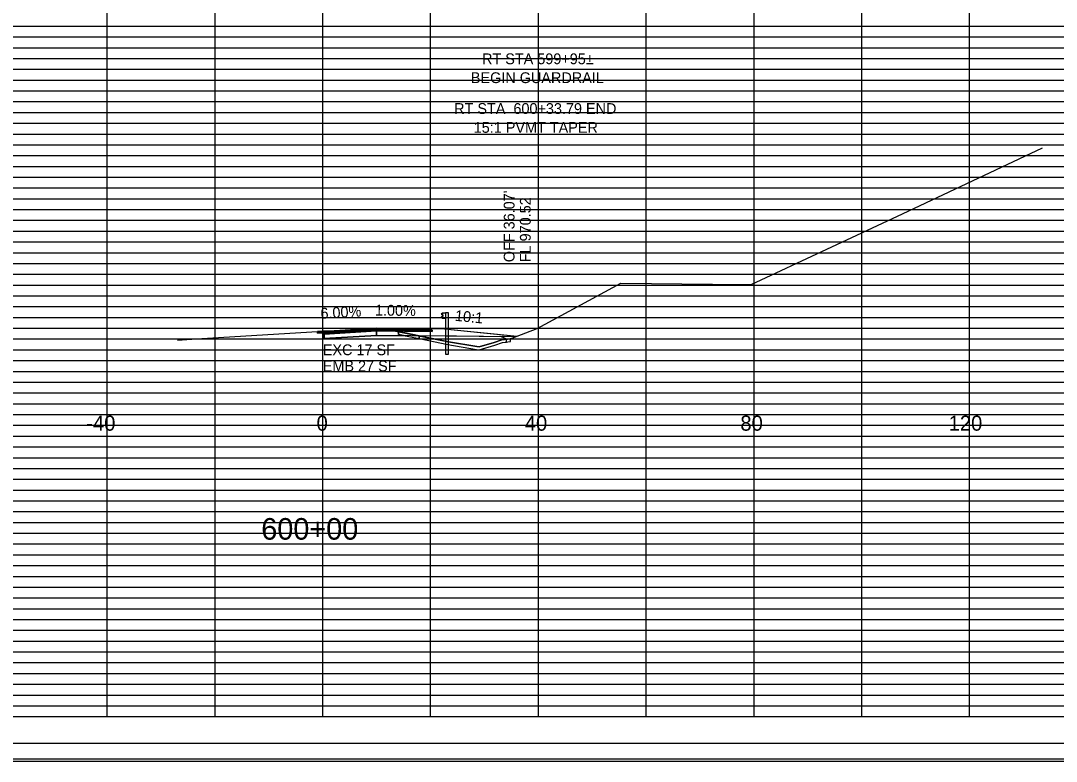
# Model space of a CAD drawing. Extents: x 2313580 to 2322968, y 282099 to 303247.
# Drawn here: x 2317145.2 to 2317337.4, y 287579.4 to 287716.7 of the extents above; entities that cross this region are included whole.
import ezdxf

# ---------------------------------------------------------------- set-up
doc = ezdxf.new("R2010")
doc.units = 0
for name, color, linetype in [('DESIGN - CENTERLINE - Proposed', 7, 'Continuous'), ('DESIGN - DRAINAGE - Text', 7, 'Continuous'), ('DESIGN - EARTHWORK - Excavation Limit Lines', 7, 'Continuous'), ('DESIGN - EARTHWORK - Shapes', 7, 'Continuous'), ('DESIGN - SCRATCH - User 5', 7, 'Continuous'), ('DESIGN - SHEET - Light Grid', 7, 'Continuous'), ('DESIGN - SHEET - Linework', 7, 'Continuous'), ('DESIGN - SHEET - Plot Shape', 7, 'Continuous'), ('DESIGN - TRANSPORTATION - Text', 7, 'Continuous'), ('DESIGN - TYPICAL - Finished Grade and Subgrade', 7, 'Continuous'), ('DESIGN - TYPICAL - Finished Grade Slopes Text', 7, 'Continuous'), ('DESIGN - TYPICAL - Guardrail', 7, 'Continuous'), ('DESIGN - TYPICAL - Text', 7, 'Continuous'), ('Scratch Level', 7, 'Continuous'), ('SURVEY - GROUND - Top of Ground', 7, 'Continuous')]:
    doc.layers.add(name, color=color, linetype=linetype)

# ---------------------------------------------------------------- blocks, each defined once
blk = doc.blocks.new('GRTYP')
at = {"layer": 'DESIGN - CENTERLINE - Proposed'}
for p, q in [((0.162, 0.37), (0.162, 0.37)), ((0.162, 0.37), (0.162, 0.37)), ((0.264, 0.37), (0.264, 0.37)), ((0.264, 0.37), (0.264, 0.37))]:
    blk.add_line(p, q, dxfattribs=at)
for points in [[(0.059, 0.567), (0.04, 0.563), (0.004, 0.539), (0, 0.531), (0.004, 0.523), (0.055, 0.492), (0.059, 0.484), (0.059, 0.464), (0.055, 0.456), (0.004, 0.425), (0, 0.417), (0.004, 0.409), (0.04, 0.385), (0.059, 0.382)], [(0.162, 0.374), (0.059, 0.374), (0.059, 0.574), (0.162, 0.574)], [(0.264, -0.126), (0.264, 0.574), (0.162, 0.574), (0.162, -0.075)], [(0.162, -0.075), (0.162, -0.949), (0.264, -0.949), (0.264, -0.122)]]:
    blk.add_lwpolyline(points, dxfattribs=at)

msp = doc.modelspace()

# ---------------------------------------------------------------- linework, layer by layer
at = {"layer": 'DESIGN - EARTHWORK - Shapes'}
for points in [[(2317216.53, 287658.28), (2317215.34, 287658.52), (2317215.34, 287659.03), (2317213.53, 287659.39), (2317207.54, 287659.33), (2317201.3, 287659.13), (2317200.3, 287659.07), (2317200.3, 287658.97), (2317200.3, 287658.76), (2317201.51, 287658.82), (2317201.51, 287658.57), (2317201.51, 287657.74), (2317211.26, 287658.33)], [(2317219.17, 287658.25), (2317224.59, 287657.15), (2317229.87, 287656.25), (2317230.27, 287656.2), (2317233.05, 287657.02), (2317234.49, 287657.49), (2317236.03, 287657.69), (2317237.03, 287658.07)]]:
    msp.add_lwpolyline(points, close=True, dxfattribs=at)
at = {"layer": 'DESIGN - SCRATCH - User 5'}
for points in [[(2317219.17, 287658.25), (2317215.34, 287659.03), (2317215.34, 287658.52), (2317219.17, 287657.74)], [(2317219.17, 287658.25), (2317215.34, 287659.03), (2317215.34, 287658.52), (2317219.17, 287657.74)], [(2317219.17, 287657.74), (2317224.5, 287656.66), (2317229.79, 287655.75), (2317230.31, 287655.69), (2317233.2, 287656.54), (2317234.6, 287657), (2317235.38, 287657.1), (2317235.38, 287657.61), (2317234.49, 287657.49), (2317233.05, 287657.02), (2317230.27, 287656.2), (2317229.87, 287656.25), (2317224.59, 287657.15), (2317219.17, 287658.25)], [(2317219.17, 287657.74), (2317224.5, 287656.66), (2317229.79, 287655.75), (2317230.31, 287655.69), (2317233.2, 287656.54), (2317234.6, 287657), (2317236.11, 287657.2), (2317236.11, 287657.72), (2317236.03, 287657.69), (2317234.49, 287657.49), (2317233.05, 287657.02), (2317230.27, 287656.2), (2317229.87, 287656.25), (2317224.59, 287657.15), (2317219.17, 287658.25)]]:
    msp.add_lwpolyline(points, close=True, dxfattribs=at)
at = {"layer": 'DESIGN - SHEET - Light Grid'}
for p, q in [((2317041.28, 287715.67), (2317201.28, 287715.67)), ((2317201.28, 287715.67), (2317361.28, 287715.67)), ((2317041.28, 287713.67), (2317201.28, 287713.67)), ((2317201.28, 287713.67), (2317361.28, 287713.67)), ((2317041.28, 287711.67), (2317201.28, 287711.67)), ((2317201.28, 287711.67), (2317361.28, 287711.67)), ((2317041.28, 287709.67), (2317201.28, 287709.67)), ((2317201.28, 287709.67), (2317361.28, 287709.67)), ((2317041.28, 287705.67), (2317201.28, 287705.67)), ((2317201.28, 287705.67), (2317361.28, 287705.67)), ((2317041.28, 287703.67), (2317201.28, 287703.67)), ((2317201.28, 287703.67), (2317361.28, 287703.67)), ((2317041.28, 287701.67), (2317201.28, 287701.67)), ((2317201.28, 287701.67), (2317361.28, 287701.67)), ((2317041.28, 287699.67), (2317201.28, 287699.67)), ((2317201.28, 287699.67), (2317361.28, 287699.67)), ((2317041.28, 287697.67), (2317201.28, 287697.67)), ((2317201.28, 287697.67), (2317361.28, 287697.67)), ((2317041.28, 287695.67), (2317201.28, 287695.67)), ((2317201.28, 287695.67), (2317361.28, 287695.67)), ((2317041.28, 287693.67), (2317201.28, 287693.67)), ((2317201.28, 287693.67), (2317361.28, 287693.67)), ((2317041.28, 287691.67), (2317201.28, 287691.67)), ((2317201.28, 287691.67), (2317361.28, 287691.67)), ((2317041.28, 287689.67), (2317201.28, 287689.67)), ((2317201.28, 287689.67), (2317361.28, 287689.67)), ((2317041.28, 287685.67), (2317201.28, 287685.67)), ((2317201.28, 287685.67), (2317361.28, 287685.67)), ((2317041.28, 287683.67), (2317201.28, 287683.67)), ((2317201.28, 287683.67), (2317361.28, 287683.67)), ((2317041.28, 287681.67), (2317201.28, 287681.67)), ((2317201.28, 287681.67), (2317361.28, 287681.67)), ((2317041.28, 287679.67), (2317201.28, 287679.67)), ((2317201.28, 287679.67), (2317361.28, 287679.67)), ((2317041.28, 287677.67), (2317201.28, 287677.67)), ((2317201.28, 287677.67), (2317361.28, 287677.67)), ((2317041.28, 287675.67), (2317201.28, 287675.67)), ((2317201.28, 287675.67), (2317361.28, 287675.67)), ((2317041.28, 287673.67), (2317201.28, 287673.67)), ((2317201.28, 287673.67), (2317361.28, 287673.67)), ((2317041.28, 287671.67), (2317201.28, 287671.67)), ((2317201.28, 287671.67), (2317361.28, 287671.67)), ((2317041.28, 287669.67), (2317201.28, 287669.67)), ((2317201.28, 287669.67), (2317361.28, 287669.67)), ((2317041.28, 287665.67), (2317201.28, 287665.67)), ((2317201.28, 287665.67), (2317361.28, 287665.67)), ((2317041.28, 287663.67), (2317201.28, 287663.67)), ((2317201.28, 287663.67), (2317361.28, 287663.67)), ((2317041.28, 287661.67), (2317201.28, 287661.67)), ((2317201.28, 287661.67), (2317361.28, 287661.67)), ((2317041.28, 287659.67), (2317201.28, 287659.67)), ((2317201.28, 287659.67), (2317361.28, 287659.67)), ((2317041.28, 287657.67), (2317201.28, 287657.67)), ((2317201.28, 287657.67), (2317361.28, 287657.67)), ((2317041.28, 287655.67), (2317201.28, 287655.67)), ((2317201.28, 287655.67), (2317361.28, 287655.67)), ((2317041.28, 287653.67), (2317201.28, 287653.67)), ((2317201.28, 287653.67), (2317361.28, 287653.67)), ((2317041.28, 287651.67), (2317201.28, 287651.67)), ((2317201.28, 287651.67), (2317361.28, 287651.67)), ((2317041.28, 287649.67), (2317201.28, 287649.67)), ((2317201.28, 287649.67), (2317361.28, 287649.67)), ((2317041.28, 287645.67), (2317201.28, 287645.67)), ((2317201.28, 287645.67), (2317361.28, 287645.67)), ((2317041.28, 287643.67), (2317201.28, 287643.67)), ((2317201.28, 287643.67), (2317361.28, 287643.67)), ((2317041.28, 287641.67), (2317201.28, 287641.67)), ((2317201.28, 287641.67), (2317361.28, 287641.67)), ((2317041.28, 287639.67), (2317201.28, 287639.67)), ((2317201.28, 287639.67), (2317361.28, 287639.67)), ((2317041.28, 287637.67), (2317201.28, 287637.67)), ((2317201.28, 287637.67), (2317361.28, 287637.67)), ((2317041.28, 287635.67), (2317201.28, 287635.67)), ((2317201.28, 287635.67), (2317361.28, 287635.67)), ((2317041.28, 287633.67), (2317201.28, 287633.67)), ((2317201.28, 287633.67), (2317361.28, 287633.67)), ((2317041.28, 287631.67), (2317201.28, 287631.67)), ((2317201.28, 287631.67), (2317361.28, 287631.67)), ((2317041.28, 287629.67), (2317201.28, 287629.67)), ((2317201.28, 287629.67), (2317361.28, 287629.67)), ((2317041.28, 287625.67), (2317201.28, 287625.67)), ((2317201.28, 287625.67), (2317361.28, 287625.67)), ((2317041.28, 287623.67), (2317201.28, 287623.67)), ((2317201.28, 287623.67), (2317361.28, 287623.67)), ((2317041.28, 287621.67), (2317201.28, 287621.67)), ((2317201.28, 287621.67), (2317361.28, 287621.67)), ((2317041.28, 287619.67), (2317201.28, 287619.67)), ((2317201.28, 287619.67), (2317361.28, 287619.67)), ((2317041.28, 287617.67), (2317201.28, 287617.67)), ((2317201.28, 287617.67), (2317361.28, 287617.67)), ((2317041.28, 287615.67), (2317201.28, 287615.67)), ((2317201.28, 287615.67), (2317361.28, 287615.67)), ((2317041.28, 287613.67), (2317201.28, 287613.67)), ((2317201.28, 287613.67), (2317361.28, 287613.67)), ((2317041.28, 287611.67), (2317201.28, 287611.67)), ((2317201.28, 287611.67), (2317361.28, 287611.67)), ((2317041.28, 287609.67), (2317201.28, 287609.67)), ((2317201.28, 287609.67), (2317361.28, 287609.67)), ((2317041.28, 287605.67), (2317201.28, 287605.67)), ((2317201.28, 287605.67), (2317361.28, 287605.67)), ((2317041.28, 287603.67), (2317201.28, 287603.67)), ((2317201.28, 287603.67), (2317361.28, 287603.67)), ((2317041.28, 287601.67), (2317201.28, 287601.67)), ((2317201.28, 287601.67), (2317361.28, 287601.67)), ((2317041.28, 287599.67), (2317201.28, 287599.67)), ((2317201.28, 287599.67), (2317361.28, 287599.67)), ((2317041.28, 287597.67), (2317201.28, 287597.67)), ((2317201.28, 287597.67), (2317361.28, 287597.67)), ((2317041.28, 287595.67), (2317201.28, 287595.67)), ((2317201.28, 287595.67), (2317361.28, 287595.67)), ((2317041.28, 287593.67), (2317201.28, 287593.67)), ((2317201.28, 287593.67), (2317361.28, 287593.67)), ((2317041.28, 287591.67), (2317201.28, 287591.67)), ((2317201.28, 287591.67), (2317361.28, 287591.67)), ((2317041.28, 287589.67), (2317201.28, 287589.67)), ((2317201.28, 287589.67), (2317361.28, 287589.67))]:
    msp.add_line(p, q, dxfattribs=at)
at = {"layer": 'DESIGN - SHEET - Linework'}
for p, q in [((2317161.28, 287587.67), (2317161.28, 288007.67)), ((2317181.28, 287587.67), (2317181.28, 288007.67)), ((2317201.28, 287587.67), (2317201.28, 288007.67)), ((2317221.28, 287587.67), (2317221.28, 288007.67)), ((2317241.28, 287587.67), (2317241.28, 288007.67)), ((2317261.28, 287587.67), (2317261.28, 288007.67)), ((2317281.28, 287587.67), (2317281.28, 288007.67)), ((2317301.28, 287587.67), (2317301.28, 288007.67)), ((2317321.28, 287587.67), (2317321.28, 288007.67)), ((2316881.28, 287707.67), (2317521.28, 287707.67)), ((2316881.28, 287687.67), (2317521.28, 287687.67)), ((2316881.28, 287667.67), (2317521.28, 287667.67)), ((2316881.28, 287647.67), (2317521.28, 287647.67)), ((2316881.28, 287627.67), (2317521.28, 287627.67)), ((2316881.28, 287607.67), (2317521.28, 287607.67)), ((2316844.82, 287579.39), (2317525.62, 287579.39))]:
    msp.add_line(p, q, dxfattribs=at)
msp.add_lwpolyline([(2316881.28, 288007.67), (2316881.28, 287587.67), (2317521.28, 287587.67), (2317521.28, 288007.67), (2316881.28, 288007.67)], dxfattribs=at)
at = {"layer": 'DESIGN - SHEET - Plot Shape'}
for points in [[(2316845.22, 288015.55), (2317525.22, 288015.55), (2317525.22, 287579.79), (2316845.22, 287579.79)], [(2316864.28, 288007.67), (2317521.28, 288007.67), (2317521.28, 287582.67), (2316864.28, 287582.67)]]:
    msp.add_lwpolyline(points, close=True, dxfattribs=at)
at = {"layer": 'DESIGN - TYPICAL - Finished Grade and Subgrade'}
msp.add_lwpolyline([(2317200.3, 287659.07), (2317201.37, 287659.13), (2317201.51, 287659.13), (2317210.02, 287659.64), (2317211.26, 287659.72), (2317220.04, 287659.63), (2317221.26, 287659.62), (2317223.26, 287659.6), (2317231.11, 287658.81), (2317233.55, 287658.57), (2317234.58, 287658.47), (2317235.44, 287658.38), (2317237.35, 287658.19)], dxfattribs=at)
for points in [[(2317201.51, 287659.13), (2317200.3, 287659.07), (2317200.3, 287658.97), (2317201.51, 287659.03)], [(2317201.51, 287659.03), (2317201.51, 287658.82), (2317200.3, 287658.76), (2317200.3, 287658.97)], [(2317201.51, 287659.13), (2317211.26, 287659.72), (2317211.26, 287659.62), (2317201.51, 287659.03)], [(2317201.51, 287659.03), (2317211.26, 287659.62), (2317211.26, 287659.41), (2317201.51, 287658.82)], [(2317201.51, 287658.82), (2317211.26, 287659.41), (2317211.26, 287659.16), (2317201.51, 287658.57)], [(2317201.51, 287658.57), (2317211.26, 287659.16), (2317211.26, 287658.33), (2317201.51, 287657.74)], [(2317211.26, 287659.62), (2317221.36, 287659.52), (2317221.36, 287659.32), (2317211.26, 287659.41)], [(2317211.26, 287659.16), (2317221.57, 287659.07), (2317221.57, 287659.32), (2317221.36, 287659.32), (2317221.36, 287659.52), (2317221.26, 287659.52), (2317221.26, 287659.62), (2317223.26, 287659.6), (2317237.35, 287658.19), (2317237.03, 287658.07), (2317211.26, 287658.33)], [(2317211.26, 287659.41), (2317221.57, 287659.32), (2317221.57, 287659.07), (2317211.26, 287659.16)]]:
    msp.add_lwpolyline(points, close=True, dxfattribs=at)
at = {"layer": 'Scratch Level'}
for points in [[(2317216.53, 287658.28), (2317215.34, 287658.52), (2317215.34, 287659.03), (2317213.53, 287659.39), (2317207.54, 287659.33), (2317201.3, 287659.13), (2317200.3, 287659.07), (2317200.3, 287658.97), (2317200.3, 287658.76), (2317201.51, 287658.82), (2317201.51, 287658.57), (2317201.51, 287657.74), (2317211.26, 287658.33)], [(2317219.17, 287658.25), (2317224.59, 287657.15), (2317229.87, 287656.25), (2317230.27, 287656.2), (2317233.05, 287657.02), (2317234.49, 287657.49), (2317235.38, 287657.61), (2317234.87, 287657.87), (2317234.41, 287658.1), (2317226.06, 287658.18)]]:
    msp.add_lwpolyline(points, close=True, dxfattribs=at)
at = {"layer": 'SURVEY - GROUND - Top of Ground'}
msp.add_lwpolyline([(2317174.34, 287657.47), (2317174.34, 287657.47), (2317177.83, 287657.71), (2317201.3, 287659.13), (2317207.54, 287659.33), (2317213.53, 287659.39), (2317224.59, 287657.15), (2317229.87, 287656.25), (2317230.27, 287656.2), (2317233.05, 287657.02), (2317234.49, 287657.49), (2317236.03, 287657.69), (2317241.06, 287659.59), (2317256.57, 287668.05), (2317273.57, 287667.83), (2317280.76, 287667.8), (2317308.83, 287680.9), (2317334.82, 287693.11)], dxfattribs=at)

# ---------------------------------------------------------------- block references
at = {"layer": 'DESIGN - TYPICAL - Guardrail', "xscale": 5, "yscale": 5}
msp.add_blockref('GRTYP', (2317223.26, 287659.63), dxfattribs=at)

# ---------------------------------------------------------------- texts
at = {"layer": 'DESIGN - DRAINAGE - Text'}
for s, p in [("OFF 36.07'", (2317236.85, 287671.9)), ('FL 970.52', (2317239.85, 287671.9))]:
    msp.add_text(s, height=2, rotation=90, dxfattribs=at).set_placement(p)
at = {"layer": 'DESIGN - EARTHWORK - Excavation Limit Lines'}
for s, p in [('EXC 17 SF', (2317201.28, 287654.67)), ('EMB 27 SF', (2317201.28, 287651.67))]:
    msp.add_text(s, height=2, dxfattribs=at).set_placement(p)
at = {"layer": 'DESIGN - TRANSPORTATION - Text'}
for s, p in [('RT STA 599+95%%P', (2317230.82, 287708.61)), ('BEGIN GUARDRAIL', (2317228.75, 287705.11)), ('RT STA  600+33.79 END', (2317225.65, 287699.39)), ('15:1 PVMT TAPER', (2317229.28, 287695.89))]:
    msp.add_text(s, height=2, dxfattribs=at).set_placement(p)
at = {"layer": 'DESIGN - TYPICAL - Finished Grade Slopes Text'}
for s, rotation, p in [('6.00%', 3.4349, (2317200.9, 287661.4)), ('1.00%', 359.4288, (2317210.94, 287662.02)), ('10:1', 354.2894, (2317225.73, 287661.05))]:
    msp.add_text(s, height=2, rotation=rotation, dxfattribs=at).set_placement(p)
at = {"layer": 'DESIGN - TYPICAL - Text'}
for s, height, p in [('-40', 2.8, (2317157.39, 287640.67)), ('0', 2.8, (2317200.12, 287640.67)), ('40', 2.8, (2317238.75, 287640.67)), ('80', 2.8, (2317278.75, 287640.67)), ('120', 2.8, (2317317.39, 287640.67)), ('600+00', 4, (2317189.86, 287620.47))]:
    msp.add_text(s, height=height, dxfattribs=at).set_placement(p)

doc.saveas('drawing.dxf')
